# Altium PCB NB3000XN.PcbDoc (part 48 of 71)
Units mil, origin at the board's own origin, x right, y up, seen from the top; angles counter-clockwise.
Board outline 9527.56 x 6929.77 mil, 6 copper layers (Top Layer, GND+SHIELD, MidLayer1, MidLayer2, P2 - 3V3+5V0, Bottom Layer), stack 62.375 mil thick; 832 components, 1027 nets, 4655 pads, 4981 vias.
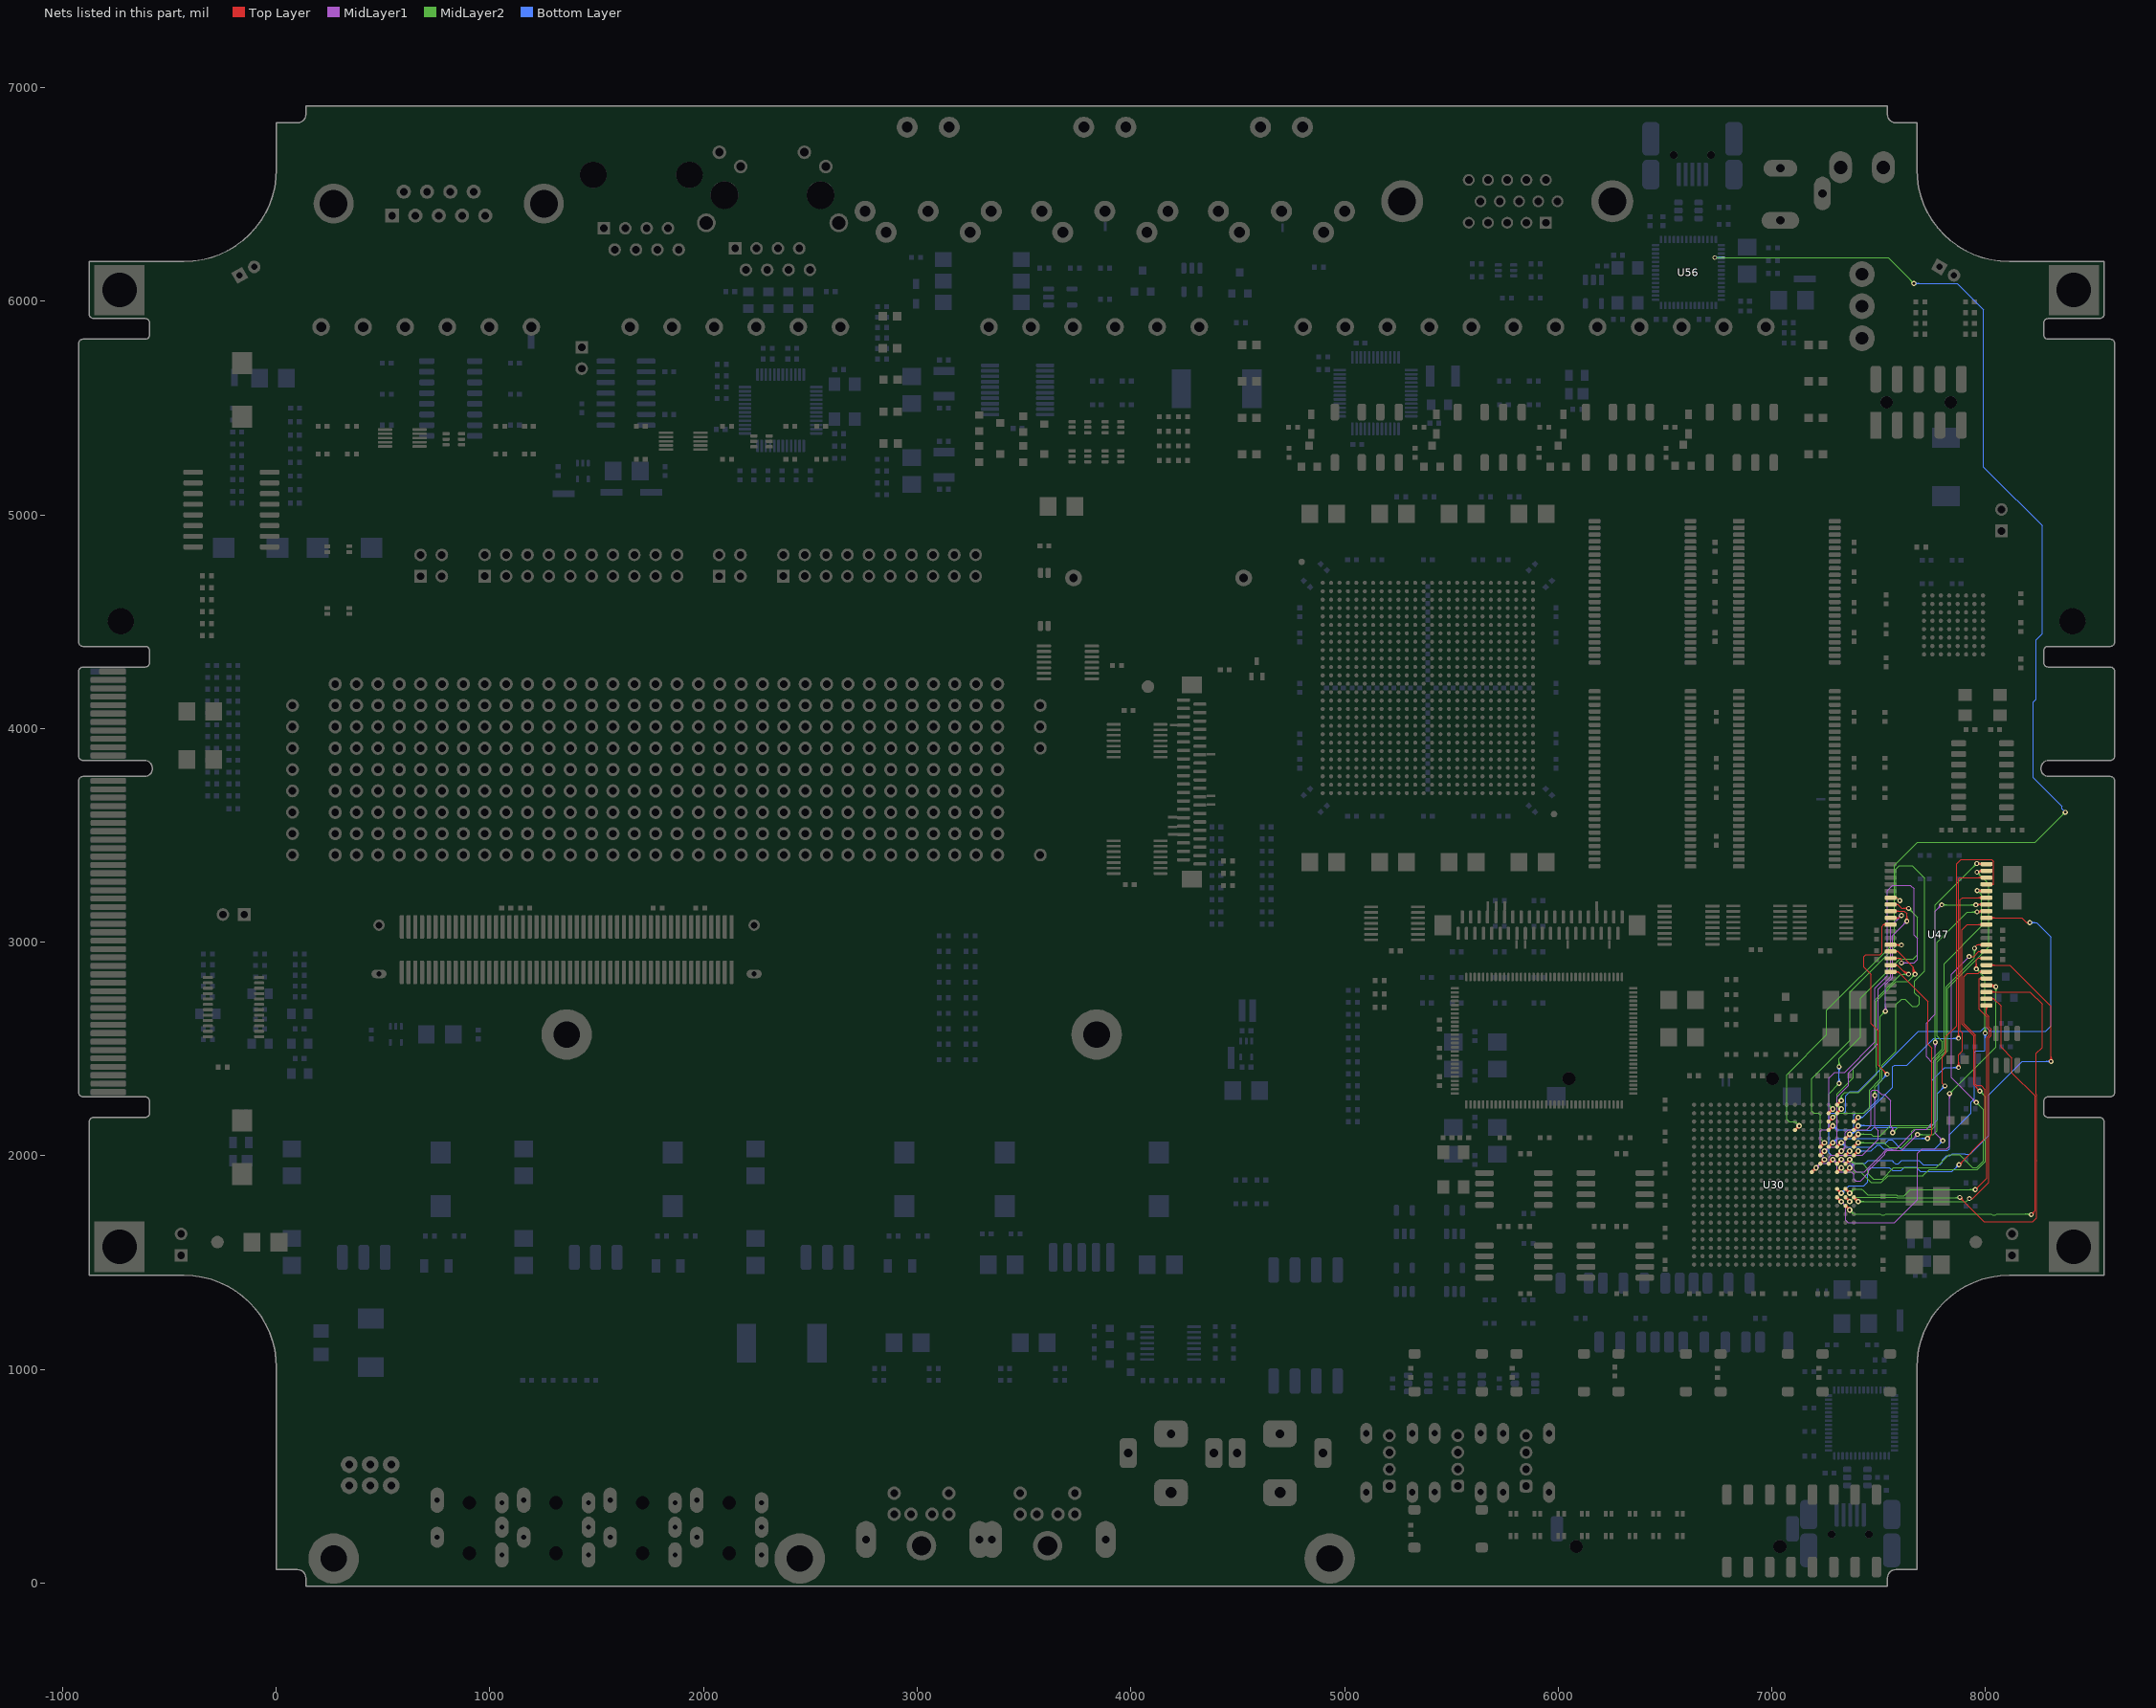
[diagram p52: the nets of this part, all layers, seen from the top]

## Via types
v1: diameter 23, hole 11.81, Top Layer to Bottom Layer, 3672 vias
v2: diameter 26, hole 11.81, Top Layer to Bottom Layer, 461 vias
v3: diameter 19, hole 11.81, Top Layer to Bottom Layer, tented both sides, 396 vias
v4: diameter 23.62, hole 11.81, Top Layer to Bottom Layer, 288 vias
v5: diameter 20, hole 11.81, Top Layer to Bottom Layer, 91 vias
v6: diameter 23, hole 11.81, Top Layer to Bottom Layer, tented both sides, 50 vias
v7: diameter 31, hole 11.81, Top Layer to Bottom Layer, 15 vias
v8: diameter 27.56, hole 11.81, Top Layer to Bottom Layer, tented both sides, 4 vias
v9: diameter 29, hole 11.81, Top Layer to Bottom Layer, 3 vias
v10: diameter 21, hole 11.81, Top Layer to Bottom Layer, 1 vias

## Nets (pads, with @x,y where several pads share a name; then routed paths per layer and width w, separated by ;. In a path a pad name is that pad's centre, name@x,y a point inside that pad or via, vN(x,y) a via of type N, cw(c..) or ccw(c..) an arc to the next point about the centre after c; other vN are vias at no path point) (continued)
HOST_SRAM.A10: U30.A12 U47.23 | length 1673.8
  Top Layer w4: v1(7924.52,1800.04) 7940.19,1800.04 8015.19,1875.04 8015.19,2551.39 8026.19,2562.39 8026.19,2593.36 8015.19,2604.36 8015.19,2652.98 8004.41,2663.76 U47.23@8004.41,2704.29 ; U47.23@7998.75,2698.64 cw(c7985.1,2684.98) 8004.41,2684.98 cw(c8023.72,2684.98) U47.23@8010.07,2698.64
  Top Layer w8: U30.A12@7384.02,1800.1 cw(c7384.02,1786) 7393.99,1795.97 cw(c7403.96,1805.94) U30.A12@7389.86,1805.94 ; U30.A12@7384.02,1805.94 v2(7403.7,1786.26) ; v2@7394.7,1786.26 ccw(c7372.97,1786.26) 7388.34,1801.62 ccw(c7403.7,1816.99) v2@7403.7,1795.26
  MidLayer2 w4: v2(7403.7,1786.26) 7910.74,1786.26 v1(7924.52,1800.04) ; v2@7408.65,1781.31 cw(c7420.6,1769.36) 7420.6,1786.26 cw(c7420.6,1803.16) v2@7408.65,1791.21 ; v2@7411.48,1778.48 cw(c7430.26,1759.7) 7430.26,1786.26 cw(c7430.26,1812.82) v2@7411.48,1794.04
HOST_SRAM.A11: U30.B13 U47.24 | length 2286.6
  Top Layer w4: U47.24@8004.41,2735.79 8038.52,2735.79 ; U47.24@8028.24,2730.82 cw(c8038.52,2722.66) 8038.52,2735.79 ; U47.24@8028.24,2740.76 ccw(c8038.52,2748.92) 8038.52,2735.79 ; v1(8213.86,1725.04) 8231.86,1743.04 8231.86,2280.52 8123.52,2388.85 8123.52,2458.37 8073.52,2508.37 8073.52,2700.79 8038.52,2735.79 ; v1@8213.86,1730.54 ccw(c8213.86,1743.82) 8223.25,1734.43 ccw(c8232.64,1725.04) v1@8219.36,1725.04 ; v1@8213.86,1734.54 ccw(c8213.86,1757.48) 8230.07,1741.26 ccw(c8246.29,1725.04) v1@8223.36,1725.04
  Top Layer w8: U30.B13@7344.65,1760.73 cw(c7344.65,1746.63) 7354.62,1756.6 cw(c7364.59,1766.57) U30.B13@7350.49,1766.57 ; U30.B13@7344.65,1766.57 v2(7364.33,1746.89) ; v2@7355.33,1746.89 ccw(c7333.6,1746.89) 7348.97,1762.25 ccw(c7364.33,1777.62) v2@7364.33,1755.89
  MidLayer2 w4: v2@7364.33,1735.89 cw(c7364.33,1709.33) 7383.11,1728.11 cw(c7401.89,1746.89) v2@7375.33,1746.89 ; v2@7364.33,1739.89 cw(c7364.33,1722.99) 7376.28,1734.94 cw(c7388.23,1746.89) v2@7371.33,1746.89 ; v2(7364.33,1746.89) 7383.51,1727.71 7507.1,1727.71 7512.62,1722.19 7527.38,1722.19 7532.9,1727.71 8027.1,1727.71 8032.62,1722.19 8047.38,1722.19 8052.9,1727.71 8211.19,1727.71 v1(8213.86,1725.04) ; 8184.48,1727.71 cw(c8184.48,1695.67) v1@8207.14,1718.32 ; 8194.14,1727.71 cw(c8194.14,1705.32) v1@8209.97,1721.15 ; 8197.36,1727.71 ccw(c8197.36,1741.54) v1@8207.14,1731.76
HOST_SRAM.A12: U30.B12 U47.25 | length 2457.9
  Top Layer w4: v1@7879.86,1795.87 cw(c7879.86,1772.94) 7896.07,1789.16 cw(c7912.29,1805.37) v1@7889.36,1805.37 ; v1@7879.86,1799.87 cw(c7879.86,1786.6) 7889.25,1795.99 cw(c7898.64,1805.37) v1@7885.36,1805.37 ; v1(7879.86,1805.37) 7993.52,1691.71 8221.86,1691.71 8240.19,1710.04 8240.19,1977.41 8240.03,1977.57 8240.03,1989.17 8240.19,1989.34 8240.19,2283.5 8237,2286.69 8237,2479.85 8265.19,2508.04 8265.19,2709.81 8207.72,2767.28 U47.25@8004.41,2767.28 ; U47.25@8027.63,2761.63 cw(c8041.28,2747.97) 8041.28,2767.28 cw(c8041.28,2786.6) U47.25@8027.63,2772.94
  Top Layer w8: U30.B12@7344.65,1800.1 cw(c7344.65,1786) 7354.62,1795.97 cw(c7364.59,1805.94) U30.B12@7350.49,1805.94 ; U30.B12@7344.65,1805.94 v2(7364.33,1786.26) ; v2@7355.33,1786.26 ccw(c7333.6,1786.26) 7348.97,1801.62 ccw(c7364.33,1816.99) v2@7364.33,1795.26
  MidLayer2 w4: v2(7364.33,1786.26) 7364.56,1786.26 7383.67,1805.37 7583.12,1805.37 7584.31,1804.19 7878.67,1804.19 v1(7879.86,1805.37) ; 7854.06,1804.19 ccw(c7854.06,1831.17) v1@7873.14,1812.09 ; 7859.78,1804.19 cw(c7859.78,1785.3) v1@7873.14,1798.66 ; 7863.72,1804.19 ccw(c7863.72,1821.52) v1@7875.97,1809.26
HOST_SRAM.A13: U30.C12 U47.26 | length 2133.8
  Top Layer w4: U47.26@8004.41,2798.78 v1@8041.12,2798.78 ; U47.26@8007.71,2798.78 cw(c8007.71,2750.56) v1@8041.81,2784.66 ; U47.26@8017.37,2798.78 cw(c8017.37,2760.22) v1@8044.64,2787.49 ; U47.26@8027.03,2798.78 cw(c8027.03,2769.88) v1@8047.46,2790.31 ; U47.26@8027.66,2793.16 cw(c8041.12,2779.86) v1@8041.12,2798.78 ; U47.26@8027.66,2804.4 ccw(c8041.12,2817.7) v1@8041.12,2798.78 ; 8036.68,2798.78 cw(c8036.68,2779.53) v1@8050.29,2793.14 ; v1(8048.52,2791.37) v1@8041.12,2798.78
  Top Layer w8: U30.C12@7305.28,1800.1 cw(c7305.28,1786) 7315.25,1795.97 cw(c7325.22,1805.94) U30.C12@7311.12,1805.94 ; U30.C12@7305.28,1805.94 v2(7324.96,1786.26) ; v2@7315.96,1786.26 ccw(c7294.23,1786.26) 7309.6,1801.62 ccw(c7324.96,1816.99) v2@7324.96,1795.26
  MidLayer1 w4: v2(7324.96,1786.26) 7344.51,1766.71 7345.33,1765.89 7345.33,1699.65 7356.46,1688.52 7574.67,1688.52 7681.86,1795.71 7681.86,2011.71 7703.52,2033.37 7819.19,2033.37 7831.86,2046.04 v1(7831.86,2291.71) ; v1@7825.14,2284.99 cw(c7808.92,2268.77) 7831.86,2268.77 cw(c7854.79,2268.77) v1@7838.57,2284.99 ; v1@7827.97,2287.82 cw(c7818.58,2278.43) 7831.86,2278.43 cw(c7845.14,2278.43) v1@7835.75,2287.82
  MidLayer2 w4: v1(7831.86,2291.71) 8048.52,2508.37 v1(8048.52,2791.37) ; v1@7831.86,2297.21 ccw(c7831.86,2310.49) 7841.25,2301.1 ccw(c7850.64,2291.71) v1@7837.36,2291.71 ; v1@7831.86,2301.21 ccw(c7831.86,2324.14) 7848.07,2307.93 ccw(c7864.29,2291.71) v1@7841.36,2291.71 ; v1@8041.81,2784.66 cw(c8025.59,2768.44) 8048.52,2768.44 cw(c8071.46,2768.44) v1@8055.24,2784.66 ; v1@8044.64,2787.49 cw(c8035.25,2778.1) 8048.52,2778.1 cw(c8061.8,2778.1) v1@8052.41,2787.49
HOST_SRAM.A14: U30.B11 U47.27 | length 1976.1
  Top Layer w4: v1(7951.86,1841.71) 8006.86,1896.71 8006.86,2554.37 8017.86,2565.37 8017.86,2590.37 8006.86,2601.37 8006.86,2650 7970.19,2686.67 7970.19,2828.61 7971.86,2830.28 ; v1@7951.86,1847.21 ccw(c7951.86,1860.49) 7961.25,1851.1 ccw(c7970.64,1841.71) v1@7957.36,1841.71 ; v1@7951.86,1851.21 ccw(c7951.86,1874.14) 7968.07,1857.93 ccw(c7984.29,1841.71) v1@7961.36,1841.71 ; U47.27@7980.2,2825.82 ccw(c7971.86,2820.23) 7971.86,2830.28 ; U47.27@7980.2,2834.73 cw(c7971.86,2840.32) 7971.86,2830.28 ; U47.27@8004.41,2830.28 7971.86,2830.28
  Top Layer w8: U30.B11@7344.65,1839.47 cw(c7344.65,1825.37) 7354.62,1835.34 cw(c7364.59,1845.31) U30.B11@7350.49,1845.31 ; U30.B11@7344.65,1845.31 v2(7364.33,1825.63) ; v2@7355.33,1825.63 ccw(c7333.6,1825.63) 7348.97,1840.99 ccw(c7364.33,1856.36) v2@7364.33,1834.63
  MidLayer2 w4: v2(7364.33,1825.63) 7383.7,1845 7420.23,1845 7428.18,1837.05 7448.52,1816.71 7583.1,1816.71 7587.62,1812.19 7619.01,1812.19 7648.52,1841.71 v1(7951.86,1841.71) ; v2@7364.33,1832.63 ccw(c7364.33,1849.53) 7376.28,1837.58 ccw(c7388.23,1825.63) v2@7371.33,1825.63 ; v2@7364.33,1836.63 ccw(c7364.33,1863.19) 7383.11,1844.41 ccw(c7401.89,1825.63) v2@7375.33,1825.63 ; v1@7945.14,1834.99 ccw(c7928.92,1818.77) 7928.92,1841.71 ccw(c7928.92,1864.64) v1@7945.14,1848.43 ; v1@7947.97,1837.82 ccw(c7938.58,1828.43) 7938.58,1841.71 ccw(c7938.58,1854.99) v1@7947.97,1845.6
HOST_SRAM.A15: U30.A3 U47.42 | length 1813.2
  Top Layer w4: v1@7866.81,2556.76 ccw(c7850.59,2572.98) 7873.52,2572.98 ccw(c7896.46,2572.98) v1@7880.24,2556.76 ; v1@7869.64,2553.93 ccw(c7860.25,2563.32) 7873.52,2563.32 ccw(c7886.8,2563.32) v1@7877.41,2553.93 ; v1(7873.52,2550.04) 7873.52,3215 7873.52,3298.52 7877.72,3302.72 U47.42@8004.41,3302.72 ; U47.42@7981.19,3297.06 ccw(c7967.54,3283.4) 7967.54,3302.72 ccw(c7967.54,3322.03) U47.42@7981.19,3308.37
  Top Layer w8: U30.A3@7384.02,2160.28 v2(7403.7,2179.96) ; U30.A3@7384.02,2166.12 ccw(c7384.02,2180.22) 7393.99,2170.25 ccw(c7403.96,2160.28) U30.A3@7389.86,2160.28 ; v2@7394.7,2179.96 cw(c7372.97,2179.96) 7388.34,2164.6 cw(c7403.7,2149.23) v2@7403.7,2170.96
  Bottom Layer w4: v2(7403.7,2179.96) 7423.52,2179.96 ; v2@7413.03,2174.14 cw(c7423.52,2167.6) 7423.52,2179.96 ; v2@7413.03,2185.78 ccw(c7423.52,2192.32) 7423.52,2179.96 ; v1@7866.81,2543.32 ccw(c7850.59,2527.11) 7850.59,2550.04 ccw(c7850.59,2572.98) v1@7866.81,2556.76 ; v1@7869.64,2546.15 ccw(c7860.25,2536.76) 7860.25,2550.04 ccw(c7860.25,2563.32) v1@7869.64,2553.93 ; v1(7873.52,2550.04) 7756.86,2550.04 7631.86,2425.04 7573.52,2425.04 7565.19,2416.71 7565.19,2321.63 7423.52,2179.96
HOST_SRAM.A16: U30.D8 U47.43 | length 2485.4
  Top Layer w4: v1(7959.86,3328.04) 7966.03,3334.21 U47.43@8004.41,3334.21 ; v1@7960.92,3326.98 cw(c7978.38,3309.52) U47.43@7978.38,3334.21 ; v1@7963.75,3324.15 cw(c7988.04,3299.86) U47.43@7988.04,3334.21 ; v1@7966.57,3321.32 cw(c7997.69,3290.21) U47.43@7997.69,3334.21 ; U47.43@7981.19,3328.56 ccw(c7967.54,3314.9) 7967.54,3334.21 ccw(c7967.54,3353.53) U47.43@7981.19,3339.87
  Top Layer w8: U30.D8@7265.91,1963.43 v2(7285.59,1983.11) ; U30.D8@7265.91,1969.27 ccw(c7265.91,1983.37) 7275.88,1973.4 ccw(c7285.85,1963.43) U30.D8@7271.75,1963.43 ; v2@7276.59,1983.11 cw(c7254.86,1983.11) 7270.23,1967.75 cw(c7285.59,1952.38) v2@7285.59,1974.11
  MidLayer1 w4: v2@7285.59,1972.11 cw(c7285.59,1945.55) 7304.37,1964.33 cw(c7323.15,1983.11) v2@7296.59,1983.11 ; v2@7285.59,1976.11 cw(c7285.59,1959.21) 7297.54,1971.16 cw(c7309.49,1983.11) v2@7292.59,1983.11 ; v2(7285.59,1983.11) 7305.86,1962.84 7305.86,1925.04 7306.19,1924.71 7373.52,1924.71 7383.52,1914.71 7383.52,1891.71 7391.86,1883.37 7415.19,1883.37 7453.52,1921.71 7453.52,1932.37 7529.88,2008.73 7529.88,2013.78 7541.15,2025.04 7606.86,2025.04 v1(7681.86,2100.04) ; v1@7672.36,2100.04 cw(c7649.42,2100.04) 7665.64,2083.82 cw(c7681.86,2067.61) v1@7681.86,2090.54 ; v1@7676.36,2100.04 cw(c7663.08,2100.04) 7672.47,2090.65 cw(c7681.86,2081.26) v1@7681.86,2094.54
  MidLayer2 w4: v1(7681.86,2100.04) 7755,2100.04 7773.19,2118.23 7773.19,2440.77 7823.52,2491.1 7823.52,2784.71 8015.19,2976.37 8015.19,3272.71 v1(7959.86,3328.04) ; v1@7685.75,2096.15 cw(c7695.14,2086.76) 7695.14,2100.04 cw(c7695.14,2113.32) v1@7685.75,2103.93 ; v1@7688.57,2093.32 cw(c7704.79,2077.11) 7704.79,2100.04 cw(c7704.79,2122.98) v1@7688.57,2106.76 ; v1@7959.86,3318.54 cw(c7959.86,3295.61) 7976.07,3311.82 cw(c7992.29,3328.04) v1@7969.36,3328.04 ; v1@7959.86,3322.54 cw(c7959.86,3309.26) 7969.25,3318.65 cw(c7978.64,3328.04) v1@7965.36,3328.04
HOST_SRAM.A17: U30.C6 U47.44 | length 2489.4
  Top Layer w4: v1(7959.52,3368.37) 7962.19,3365.71 U47.44@8004.41,3365.71 ; v1@7963.41,3372.26 ccw(c7979.24,3388.09) U47.44@7979.24,3365.71 ; v1@7966.24,3361.66 cw(c7976.02,3351.88) 7976.02,3365.71 ; v1@7966.24,3375.09 ccw(c7988.9,3397.75) U47.44@7988.9,3365.71 ; U47.44@7981.19,3360.05 ccw(c7967.54,3346.39) 7967.54,3365.71 ccw(c7967.54,3385.02) U47.44@7981.19,3371.37
  Top Layer w8: U30.C6@7305.28,2042.17 v2(7324.96,2061.85) ; U30.C6@7305.28,2048.01 ccw(c7305.28,2062.11) 7315.25,2052.14 ccw(c7325.22,2042.17) U30.C6@7311.12,2042.17 ; v2@7315.96,2061.85 cw(c7294.23,2061.85) 7309.6,2046.49 cw(c7324.96,2031.12) v2@7324.96,2052.85
  MidLayer1 w4: v1@7758.47,2524.99 cw(c7742.26,2508.77) 7765.19,2508.77 cw(c7788.13,2508.77) v1@7771.91,2524.99 ; v1@7761.3,2527.82 cw(c7751.91,2518.43) 7765.19,2518.43 cw(c7778.47,2518.43) v1@7769.08,2527.82 ; v1(7765.19,2531.71) 7765.19,2106.37 v1(7800.52,2071.04) ; v1@7791.02,2071.04 ccw(c7768.09,2071.04) 7784.31,2087.26 ccw(c7800.52,2103.48) v1@7800.52,2080.54 ; v1@7795.02,2071.04 ccw(c7781.75,2071.04) 7791.14,2080.43 ccw(c7800.52,2089.82) v1@7800.52,2076.54
  MidLayer2 w4: v1@7758.47,2538.43 ccw(c7742.26,2554.64) 7765.19,2554.64 ccw(c7788.13,2554.64) v1@7771.91,2538.43 ; v1@7761.3,2535.6 ccw(c7751.91,2544.99) 7765.19,2544.99 ccw(c7778.47,2544.99) v1@7769.08,2535.6 ; v1(7765.19,2531.71) 7765.19,3174.04 v1(7959.52,3368.37) ; v1@7950.02,3368.37 cw(c7927.09,3368.37) 7943.31,3352.16 cw(c7959.52,3335.94) v1@7959.52,3358.87 ; v1@7954.02,3368.37 cw(c7940.75,3368.37) 7950.14,3358.99 cw(c7959.52,3349.6) v1@7959.52,3362.87
  Bottom Layer w4: v2@7324.96,2050.85 cw(c7324.96,2024.29) 7343.74,2043.07 cw(c7362.52,2061.85) v2@7335.96,2061.85 ; v2@7324.96,2054.85 cw(c7324.96,2037.95) 7336.91,2049.9 cw(c7348.86,2061.85) v2@7331.96,2061.85 ; v2(7324.96,2061.85) 7345.1,2041.71 7465.19,2041.71 7481.86,2058.37 7532.11,2058.37 7548.28,2074.54 7562.77,2074.54 7603.94,2033.37 7762.86,2033.37 v1(7800.52,2071.04) ; v1@7791.02,2071.04 cw(c7768.09,2071.04) 7784.31,2054.82 cw(c7800.52,2038.61) v1@7800.52,2061.54 ; v1@7795.02,2071.04 cw(c7781.75,2071.04) 7791.13,2061.65 cw(c7800.52,2052.26) v1@7800.52,2065.54
HOST_SRAM.A18: U30.C11 U47.28 | length 2072.5
  Top Layer w4: v1(7876.19,1958.37) 7998.52,2080.71 7998.52,2310 7978.52,2330 7957.88,2330 7953,2334.88 7953,2540 ; v1@7876.19,1963.87 ccw(c7876.19,1977.15) 7885.58,1967.76 ccw(c7894.97,1958.37) v1@7881.69,1958.37 ; v1@7876.19,1967.87 ccw(c7876.19,1990.81) 7892.41,1974.59 ccw(c7908.63,1958.37) v1@7885.69,1958.37 ; 7953,2562 7953,2540 ; U47.28@7980.23,2857.29 ccw(c7971.77,2851.56) 7971.77,2861.77 ; U47.28@7980.23,2866.26 cw(c7971.77,2871.98) 7971.77,2861.77 ; U47.28@8004.41,2861.77 7971.77,2861.77 ; 7953,2540 7953,2565.21 7898.19,2620.02 7898.19,2838 7915.19,2855 7965,2855 7971.77,2861.77
  Top Layer w8: U30.C11@7305.28,1839.47 cw(c7305.28,1825.37) 7315.25,1835.34 cw(c7325.22,1845.31) U30.C11@7311.12,1845.31 ; U30.C11@7305.28,1845.31 v2(7324.96,1825.63) ; v2@7315.96,1825.63 ccw(c7294.23,1825.63) 7309.6,1840.99 ccw(c7324.96,1856.36) v2@7324.96,1834.63
  Bottom Layer w4: v2(7324.96,1825.63) 7360.33,1861 7430.96,1861 7448.02,1878.06 7448.02,1929.27 7463.13,1944.37 7550.62,1944.37 7564.5,1930.5 7605.5,1930.5 7621.21,1946.21 7674.45,1946.21 7694.66,1926 7843.82,1926 v1(7876.19,1958.37) ; v2@7324.96,1832.63 ccw(c7324.96,1849.53) 7336.91,1837.58 ccw(c7348.86,1825.63) v2@7331.96,1825.63 ; v2@7324.96,1836.63 ccw(c7324.96,1863.19) 7343.74,1844.41 ccw(c7362.52,1825.63) v2@7335.96,1825.63 ; v1@7866.69,1958.37 cw(c7843.76,1958.37) 7859.97,1942.16 cw(c7876.19,1925.94) v1@7876.19,1948.87 ; v1@7870.69,1958.37 cw(c7857.41,1958.37) 7866.8,1948.99 cw(c7876.19,1939.6) v1@7876.19,1952.87
HOST_SRAM.D0: U30.D2 U47.7 | length 1782
  Top Layer w4: U47.7@7555.59,3176.73 7589.52,3176.73 ; U47.7@7579.46,3171.82 cw(c7589.52,3163.97) 7589.52,3176.73 ; U47.7@7579.46,3181.65 ccw(c7589.52,3189.49) 7589.52,3176.73 ; v1@7633.47,3151.66 ccw(c7617.26,3135.44) 7617.26,3158.37 ccw(c7617.26,3181.31) v1@7633.47,3165.09 ; v1@7636.3,3154.49 ccw(c7626.91,3145.1) 7626.91,3158.37 ccw(c7626.91,3171.65) v1@7636.3,3162.26 ; v1(7640.19,3158.37) 7607.88,3158.37 7589.52,3176.73
  Top Layer w8: U30.D2@7265.91,2199.65 v2(7285.59,2219.33) ; U30.D2@7265.91,2205.49 ccw(c7265.91,2219.59) 7275.88,2209.62 ccw(c7285.85,2199.65) U30.D2@7271.75,2199.65 ; v2@7276.59,2219.33 cw(c7254.86,2219.33) 7270.23,2203.97 cw(c7285.59,2188.6) v2@7285.59,2210.33
  MidLayer2 w4: v2@7274.59,2219.33 ccw(c7248.03,2219.33) 7266.81,2238.11 ccw(c7285.59,2256.89) v2@7285.59,2230.33 ; v2@7278.59,2219.33 ccw(c7261.69,2219.33) 7273.64,2231.28 ccw(c7285.59,2243.23) v2@7285.59,2226.33 ; v2(7285.59,2219.33) 7266.52,2238.4 7266.52,2290.37 v1(7315.19,2339.04) ; v1@7305.69,2339.04 cw(c7282.76,2339.04) 7298.97,2322.82 cw(c7315.19,2306.61) v1@7315.19,2329.54 ; v1@7308.47,2423.43 ccw(c7292.26,2439.64) 7315.19,2439.64 ccw(c7338.13,2439.64) v1@7321.91,2423.43 ; v1@7309.69,2339.04 cw(c7296.41,2339.04) 7305.8,2329.65 cw(c7315.19,2320.26) v1@7315.19,2333.54 ; v1@7311.3,2420.6 ccw(c7301.91,2429.99) 7315.19,2429.99 ccw(c7328.47,2429.99) v1@7319.08,2420.6 ; v1(7315.19,2416.71) 7315.19,2456.06 7415.19,2556.06 7415.19,2737.71 7599.52,2922.04 7662.19,2922.04 7681.86,2941.71 7681.86,3116.71 v1(7640.19,3158.37) ; v1@7640.19,3148.87 cw(c7640.19,3125.94) 7656.41,3142.16 cw(c7672.63,3158.37) v1@7649.69,3158.37 ; v1@7640.19,3152.87 cw(c7640.19,3139.6) 7649.58,3148.99 cw(c7658.97,3158.37) v1@7645.69,3158.37
  Bottom Layer w4: v1@7308.47,2345.76 ccw(c7292.26,2361.98) 7315.19,2361.98 ccw(c7338.13,2361.98) v1@7321.91,2345.76 ; v1@7308.47,2409.99 cw(c7292.26,2393.77) 7315.19,2393.77 cw(c7338.13,2393.77) v1@7321.91,2409.99 ; v1@7311.3,2342.93 ccw(c7301.91,2352.32) 7315.19,2352.32 ccw(c7328.47,2352.32) v1@7319.08,2342.93 ; v1@7311.3,2412.82 cw(c7301.91,2403.43) 7315.19,2403.43 cw(c7328.47,2403.43) v1@7319.08,2412.82 ; v1(7315.19,2339.04) v1(7315.19,2416.71)
HOST_SRAM.D1: U30.D3 U47.8 | length 1662.2
  Top Layer w4: U47.8@7555.59,3145.24 7620,3145.24 7631.86,3133.37 v1(7631.86,3098.04) ; U47.8@7578.81,3139.58 cw(c7592.46,3125.92) 7592.46,3145.24 cw(c7592.46,3164.55) U47.8@7578.81,3150.89 ; v1@7625.14,3104.76 ccw(c7608.92,3120.98) 7631.86,3120.98 ccw(c7654.79,3120.98) v1@7638.57,3104.76 ; v1@7627.97,3101.93 ccw(c7618.58,3111.32) 7631.86,3111.32 ccw(c7645.14,3111.32) v1@7635.75,3101.93
  Top Layer w8: U30.D3@7265.91,2160.28 v2(7285.59,2179.96) ; U30.D3@7265.91,2166.12 ccw(c7265.91,2180.22) 7275.88,2170.25 ccw(c7285.85,2160.28) U30.D3@7271.75,2160.28 ; v2@7276.59,2179.96 cw(c7254.86,2179.96) 7270.23,2164.6 cw(c7285.59,2149.23) v2@7285.59,2170.96
  MidLayer1 w4: v1@7525.14,2683.43 ccw(c7508.92,2699.64) 7531.86,2699.64 ccw(c7554.79,2699.64) v1@7538.57,2683.43 ; v1@7527.97,2680.6 ccw(c7518.58,2689.99) 7531.86,2689.99 ccw(c7545.14,2689.99) v1@7535.75,2680.6 ; v1(7531.86,2676.71) 7531.86,2801.81 7564.86,2834.81 7564.86,3031.04 v1(7631.86,3098.04) ; v1@7622.36,3098.04 cw(c7599.42,3098.04) 7615.64,3081.82 cw(c7631.86,3065.61) v1@7631.86,3088.54 ; v1@7626.36,3098.04 cw(c7613.08,3098.04) 7622.47,3088.65 cw(c7631.86,3079.26) v1@7631.86,3092.54
  MidLayer2 w4: v2(7285.59,2179.96) 7305.67,2200.04 7431.86,2200.04 7456.86,2225.04 7456.86,2308.37 7506.86,2358.37 7506.86,2651.71 v1(7531.86,2676.71) ; v2@7285.59,2186.96 ccw(c7285.59,2203.86) 7297.54,2191.91 ccw(c7309.49,2179.96) v2@7292.59,2179.96 ; v2@7285.59,2190.96 ccw(c7285.59,2217.52) 7304.37,2198.74 ccw(c7323.15,2179.96) v2@7296.59,2179.96 ; v1@7522.36,2676.71 cw(c7499.42,2676.71) 7515.64,2660.49 cw(c7531.86,2644.27) v1@7531.86,2667.21 ; v1@7526.36,2676.71 cw(c7513.08,2676.71) 7522.47,2667.32 cw(c7531.86,2657.93) v1@7531.86,2671.21
HOST_SRAM.D2: U30.E7 U47.9 | length 1570.2
  Top Layer w4: U47.9@7555.59,3113.74 7595.56,3113.74 v1(7606.86,3125.04) ; U47.9@7578.81,3108.08 cw(c7592.46,3094.43) 7592.46,3113.74 cw(c7592.46,3133.05) U47.9@7578.81,3119.4
  Top Layer w8: U30.E7@7226.54,2002.8 v2(7246.22,2022.48) ; U30.E7@7226.54,2008.64 ccw(c7226.54,2022.74) 7236.51,2012.77 ccw(c7246.48,2002.8) U30.E7@7232.38,2002.8 ; v2@7237.22,2022.48 cw(c7215.49,2022.48) 7230.86,2007.12 cw(c7246.22,1991.75) v2@7246.22,2013.48
  MidLayer1 w4: v2(7246.22,2022.48) 7265.45,2041.71 7304.19,2041.71 7305.86,2043.37 7305.86,2276.37 7360.15,2330.67 7360.15,2388.84 7498.52,2527.21 7498.52,2779.79 7556.86,2838.12 7556.86,3075.04 v1(7606.86,3125.04) ; v2@7246.22,2029.48 ccw(c7246.22,2046.38) 7258.17,2034.43 ccw(c7270.12,2022.48) v2@7253.22,2022.48 ; v2@7246.22,2033.48 ccw(c7246.22,2060.04) 7265,2041.26 ; v2@7257.22,2022.48 cw(c7283.77,2022.48) 7265,2041.26 ; v1@7597.36,3125.04 cw(c7574.42,3125.04) 7590.64,3108.82 cw(c7606.86,3092.61) v1@7606.86,3115.54 ; v1@7601.36,3125.04 cw(c7588.08,3125.04) 7597.47,3115.65 cw(c7606.86,3106.26) v1@7606.86,3119.54
HOST_SRAM.D3: U30.D4 U47.10 | length 1589.1
  Top Layer w4: v1@7530.69,2382.04 ccw(c7507.76,2382.04) 7523.97,2398.26 ccw(c7540.19,2414.48) v1@7540.19,2391.54 ; U47.10@7531.35,3077.85 ccw(c7523.19,3072.48) 7523.19,3082.24 ; U47.10@7531.35,3086.64 cw(c7523.19,3092.01) 7523.19,3082.24 ; v1@7534.69,2382.04 ccw(c7521.41,2382.04) 7530.8,2391.43 ccw(c7540.19,2400.82) v1@7540.19,2387.54 ; v1(7540.19,2382.04) 7498.52,2423.71 7498.52,2586.04 7465.19,2619.37 7465.19,2850.04 7431.86,2883.37 7431.86,2933.37 7440.19,2941.71 7506.86,2941.71 7515.19,2950.04 7515.19,3074.24 7523.19,3082.24 ; U47.10@7555.59,3082.24 7523.19,3082.24
  Top Layer w8: U30.D4@7265.91,2120.91 v2(7285.59,2140.59) ; U30.D4@7265.91,2126.75 ccw(c7265.91,2140.85) 7275.88,2130.88 ccw(c7285.85,2120.91) U30.D4@7271.75,2120.91 ; v2@7276.59,2140.59 cw(c7254.86,2140.59) 7270.23,2125.23 cw(c7285.59,2109.86) v2@7285.59,2131.59
  Bottom Layer w4: v2@7285.59,2129.59 cw(c7285.59,2103.03) 7304.37,2121.81 cw(c7323.14,2140.59) v2@7296.59,2140.59 ; v2@7285.59,2133.59 cw(c7285.59,2116.69) 7297.54,2128.64 cw(c7309.49,2140.59) v2@7292.59,2140.59 ; v2(7285.59,2140.59) 7305.14,2121.04 7373.52,2121.04 7383.86,2131.37 7383.86,2191.71 7392.19,2200.04 7431.86,2200.04 7499.86,2268.04 7499.86,2341.71 v1(7540.19,2382.04) ; v1@7530.69,2382.04 cw(c7507.76,2382.04) 7523.97,2365.82 cw(c7540.19,2349.61) v1@7540.19,2372.54 ; v1@7534.69,2382.04 cw(c7521.41,2382.04) 7530.8,2372.65 cw(c7540.19,2363.26) v1@7540.19,2376.54
HOST_SRAM.D4: U30.E6 U47.13 | length 1379.6
  Top Layer w4: U47.13@7555.59,2987.76 7589.52,2987.76 ; U47.13@7579.46,2982.84 cw(c7589.52,2975) 7589.52,2987.76 ; U47.13@7579.46,2992.67 ccw(c7589.52,3000.51) 7589.52,2987.76 ; v1@7598.59,2982.03 ccw(c7590.57,2977.5) 7590.57,2986.71 ; v1@7598.59,2991.38 cw(c7590.57,2995.92) 7590.57,2986.71 ; v1(7606.86,2986.71) 7590.57,2986.71 ; 7589.52,2987.76 7590.57,2986.71
  Top Layer w8: U30.E6@7226.54,2042.17 v2(7246.22,2061.85) ; U30.E6@7226.54,2048.01 ccw(c7226.54,2062.11) 7236.51,2052.14 ccw(c7246.48,2042.17) U30.E6@7232.38,2042.17 ; v2@7237.22,2061.85 cw(c7215.49,2061.85) 7230.86,2046.49 cw(c7246.22,2031.12) v2@7246.22,2052.85
  MidLayer2 w4: v2(7246.22,2061.85) 7227.19,2080.88 7227.19,2191.71 7218.86,2200.04 7195.86,2200.04 7187.52,2208.37 7187.52,2362.33 7366.19,2541 7366.19,2767.71 7585.19,2986.71 ; v1@7599.87,2980.27 ccw(c7585.19,2966.75) 7585.19,2986.71 ; v1@7599.87,2993.14 cw(c7585.19,3006.66) 7585.19,2986.71 ; v1@7602.81,2982.98 ccw(c7594.31,2975.15) 7594.31,2986.71 ccw(c7594.31,2998.26) v1@7602.81,2990.43 ; v1(7606.86,2986.71) 7585.19,2986.71
HOST_SRAM.D5: U30.C1 U47.14 | length 1277.1
  Top Layer w4: U47.14@7555.59,2956.26 7588.82,2956.26 ; U47.14@7579.63,2951.57 cw(c7588.82,2944.92) 7588.82,2956.26 ; U47.14@7579.63,2960.95 ccw(c7588.82,2967.6) 7588.82,2956.26 ; 7661.86,2860.89 ccw(c7677.37,2860.89) v1@7668.81,2847.96 ; 7661.86,2868.33 ccw(c7682.29,2868.33) v1@7671.02,2851.29 ; 7661.86,2875.78 ccw(c7687.21,2875.78) v1@7673.22,2854.63 ; v1(7670.19,2850.04) 7661.86,2858.37 7661.86,2883.22 ; v1@7675.43,2857.96 cw(c7692.13,2883.22) 7661.86,2883.22 ; 7588.82,2956.26 7661.86,2883.22
  Top Layer w8: U30.C1@7305.28,2239.02 v2(7324.96,2258.7) ; U30.C1@7305.28,2244.86 ccw(c7305.28,2258.96) 7315.25,2248.99 ccw(c7325.22,2239.02) U30.C1@7311.12,2239.02 ; v2@7315.96,2258.7 cw(c7294.23,2258.7) 7309.6,2243.34 cw(c7324.96,2227.97) v2@7324.96,2249.7
  MidLayer2 w4: v2@7318.61,2267.68 ccw(c7309.92,2279.96) 7324.96,2279.96 ; v2@7320.92,2264.42 ccw(c7315.39,2272.23) 7324.96,2272.23 ccw(c7334.53,2272.23) v2@7329,2264.42 ; v2(7324.96,2258.7) 7324.96,2279.96 ; v2@7331.31,2267.68 cw(c7340,2279.96) 7324.96,2279.96 ; v1@7660.69,2850.04 cw(c7637.76,2850.04) 7653.97,2833.82 cw(c7670.19,2817.61) v1@7670.19,2840.54 ; v1@7664.69,2850.04 cw(c7651.41,2850.04) 7660.8,2840.65 cw(c7670.19,2831.26) v1@7670.19,2844.54 ; v1(7670.19,2850.04) 7636.86,2816.71 7581.86,2816.71 7490.19,2725.04 7490.19,2415 7490.52,2414.67 7490.52,2381.69 7405.21,2296.37 7380,2296.37 7341.37,2296.37 7324.96,2279.96
HOST_SRAM.D6: U30.E8 U47.15 | length 2250.2
  Top Layer w4: U47.15@7555.59,2924.76 7600.24,2924.76 7606.86,2918.14 v1(7606.86,2902.71) ; U47.15@7578.81,2919.11 cw(c7592.46,2905.45) 7592.46,2924.76 cw(c7592.46,2944.08) U47.15@7578.81,2930.42
  Top Layer w8: U30.E8@7226.54,1963.43 v2(7246.22,1983.11) ; U30.E8@7226.54,1969.27 ccw(c7226.54,1983.37) 7236.51,1973.4 ccw(c7246.48,1963.43) U30.E8@7232.38,1963.43 ; v2@7237.22,1983.11 cw(c7215.49,1983.11) 7230.86,1967.75 cw(c7246.22,1952.38) v2@7246.22,1974.11
  MidLayer1 w4: v2@7238.44,1990.89 ccw(c7234.22,1995.11) 7240.19,1995.11 ; v2(7246.22,1983.11) 7240.19,1983.11 7240.19,2000.04 7226.19,2014.04 7226.19,2116.71 7230.52,2121.04 7256.86,2121.04 7266.52,2130.71 7266.52,2364.04 7294.19,2391.71 7340.39,2391.71 7481.86,2533.17 7481.86,2560 7481.86,2785.75 7540.19,2844.08 7540.19,3241.71 7565.19,3266.71 7648.52,3266.71 7665.19,3250.04 7665.19,3033.37 7681.86,3016.71 7681.86,2919.37 7665.19,2902.71 v1(7606.86,2902.71) ; v1@7610.75,2898.82 cw(c7620.14,2889.43) 7620.14,2902.71 cw(c7620.14,2915.99) v1@7610.75,2906.6 ; v1@7613.57,2895.99 cw(c7629.79,2879.77) 7629.79,2902.71 cw(c7629.79,2925.64) v1@7613.57,2909.43
HOST_SRAM.D7: U30.C2 U47.16 | length 1229.1
  Top Layer w4: U47.16@7555.59,2893.27 7587.15,2893.27 ; U47.16@7580.04,2889.21 cw(c7587.15,2885.02) 7587.15,2893.27 ; U47.16@7580.04,2897.33 ccw(c7587.15,2901.52) 7587.15,2893.27 ; 7607.22,2873.2 ccw(c7640.19,2906.17) v1@7640.19,2859.54 ; 7614.05,2866.37 ccw(c7640.19,2892.51) v1@7640.19,2855.54 ; 7620.88,2859.54 ccw(c7640.19,2878.86) v1@7640.19,2851.54 ; 7627.7,2852.71 ccw(c7640.19,2865.2) v1@7640.19,2847.54 ; v1(7640.19,2850.04) 7630.38,2850.04 7587.15,2893.27
  Top Layer w8: U30.C2@7305.28,2199.65 v2(7324.96,2219.33) ; U30.C2@7305.28,2205.49 ccw(c7305.28,2219.59) 7315.25,2209.62 ccw(c7325.22,2199.65) U30.C2@7311.12,2199.65 ; v2@7315.96,2219.33 cw(c7294.23,2219.33) 7309.6,2203.97 cw(c7324.96,2188.6) v2@7324.96,2210.33
  MidLayer2 w4: v2@7313.96,2219.33 ccw(c7287.4,2219.33) 7306.18,2238.11 ccw(c7324.96,2256.89) v2@7324.96,2230.33 ; v2@7317.96,2219.33 ccw(c7301.06,2219.33) 7313.01,2231.28 ccw(c7324.96,2243.23) v2@7324.96,2226.33 ; v2(7324.96,2219.33) 7305.86,2238.43 7305.86,2290.71 7381.86,2366.71 7381.86,2408.37 7481.86,2508.37 7481.86,2729.37 7602.52,2850.04 v1(7640.19,2850.04) ; v1@7633.47,2843.32 ccw(c7617.26,2827.11) 7617.26,2850.04 ccw(c7617.26,2872.98) v1@7633.47,2856.76 ; v1@7636.3,2846.15 ccw(c7626.91,2836.76) 7626.91,2850.04 ccw(c7626.91,2863.32) v1@7636.3,2853.93
HOST_SRAM.D8: U30.B9 U47.29 | length 2236.8
  Top Layer w4: U47.29@8004.41,2893.27 8113.63,2893.27 8306.86,2700.04 v1(8306.86,2441.71) ; U47.29@8027.63,2887.61 cw(c8041.28,2873.95) 8041.28,2893.27 cw(c8041.28,2912.58) U47.29@8027.63,2898.92 ; v1@8300.14,2448.43 ccw(c8283.92,2464.64) 8306.86,2464.64 ccw(c8329.79,2464.64) v1@8313.57,2448.43 ; v1@8302.97,2445.6 ccw(c8293.58,2454.99) 8306.86,2454.99 ccw(c8320.14,2454.99) v1@8310.75,2445.6
  Top Layer w8: U30.B9@7344.65,1924.06 v2(7364.33,1943.74) ; U30.B9@7344.65,1929.9 ccw(c7344.65,1944) 7354.62,1934.03 ccw(c7364.59,1924.06) U30.B9@7350.49,1924.06 ; v2@7355.33,1943.74 cw(c7333.6,1943.74) 7348.97,1928.38 cw(c7364.33,1913.01) v2@7364.33,1934.74
  Bottom Layer w4: v2(7364.33,1943.74) 7384.63,1964.04 7437.54,1964.04 7451.87,1978.37 7562.11,1978.37 7567.5,1972.98 7567.5,1972.75 7577.75,1962.5 7592.25,1962.5 7607.96,1978.21 7687.71,1978.21 7707.92,1958 7787.09,1958 7798.36,1969.27 7798.36,1980.58 7817.98,2000.21 7833.89,2000.21 7844.5,2010.81 7902.67,2010.81 7905.98,2007.5 7924.4,2007.5 7927.46,2010.56 7930.71,2010.56 8015.19,2095.04 8015.19,2285.04 8171.86,2441.71 v1(8306.86,2441.71) ; v2@7364.33,1950.74 ccw(c7364.33,1967.64) 7376.28,1955.69 ccw(c7388.23,1943.74) v2@7371.33,1943.74 ; v2@7364.33,1954.74 ccw(c7364.33,1981.3) 7383.11,1962.52 ccw(c7401.88,1943.74) v2@7375.33,1943.74 ; v1@8300.14,2434.99 ccw(c8283.92,2418.77) 8283.92,2441.71 ccw(c8283.92,2464.64) v1@8300.14,2448.43 ; v1@8302.97,2437.82 ccw(c8293.58,2428.43) 8293.58,2441.71 ccw(c8293.58,2454.99) v1@8302.97,2445.6
HOST_SRAM.D9: U30.A7 U47.30 | length 1908.4
  Top Layer w4: v1@7950.14,2881.76 ccw(c7933.92,2897.98) 7956.86,2897.98 ccw(c7979.79,2897.98) v1@7963.57,2881.76 ; v1@7952.97,2878.93 ccw(c7943.58,2888.32) 7956.86,2888.32 ccw(c7970.14,2888.32) v1@7960.75,2878.93 ; v1(7956.86,2875.04) 7956.86,2916.43 7965.19,2924.76 U47.30@8004.41,2924.76 ; U47.30@7981.19,2919.11 ccw(c7967.54,2905.45) 7967.54,2924.76 ccw(c7967.54,2944.08) U47.30@7981.19,2930.42
  Top Layer w8: U30.A7@7384.02,2002.8 v2(7403.7,2022.48) ; U30.A7@7384.02,2008.64 ccw(c7384.02,2022.74) 7393.99,2012.77 ccw(c7403.96,2002.8) U30.A7@7389.86,2002.8 ; v2@7394.7,2022.48 cw(c7372.97,2022.48) 7388.34,2007.12 cw(c7403.7,1991.75) v2@7403.7,2013.48
  MidLayer2 w4: v1@7956.86,2865.54 cw(c7956.86,2842.61) 7973.07,2858.82 cw(c7989.29,2875.04) v1@7966.36,2875.04 ; v1@7956.86,2869.54 cw(c7956.86,2856.26) 7966.25,2865.65 cw(c7975.64,2875.04) v1@7962.36,2875.04 ; v1(7956.86,2875.04) 7998.52,2833.37 v1(7998.52,2575.04) ; v1@7991.81,2581.76 ccw(c7975.59,2597.98) 7998.52,2597.98 ccw(c8021.46,2597.98) v1@8005.24,2581.76 ; v1@7994.64,2578.93 ccw(c7985.25,2588.32) 7998.52,2588.32 ccw(c8011.8,2588.32) v1@8002.41,2578.93
  Bottom Layer w4: v2(7403.7,2022.48) 7465.3,2022.48 7492.86,2050.04 7505.52,2050.04 7523.35,2032.21 7559.29,2032.21 7566.46,2025.04 7823.86,2025.04 7831.86,2033.04 7831.86,2100.04 7931.86,2200.04 7931.86,2251.37 7948.52,2268.04 7948.52,2485.71 7954.52,2491.71 7995.86,2491.71 7998.52,2494.37 v1(7998.52,2575.04) ; v2@7408.65,2017.53 cw(c7420.6,2005.58) 7420.6,2022.48 cw(c7420.6,2039.38) v2@7408.65,2027.43 ; v2@7411.48,2014.7 cw(c7430.26,1995.93) 7430.26,2022.48 cw(c7430.26,2049.04) v2@7411.48,2030.26 ; v1@7991.81,2568.32 cw(c7975.59,2552.11) 7998.52,2552.11 cw(c8021.46,2552.11) v1@8005.24,2568.32 ; v1@7994.64,2571.15 cw(c7985.25,2561.76) 7998.52,2561.76 cw(c8011.8,2561.76) v1@8002.41,2571.15
HOST_SRAM.D10: U30.B8 U47.31 | length 2200.1
  Top Layer w4: v1(7923.52,2933.37) 7945.97,2933.37 7968.85,2956.26 ; U47.31@7980.91,2950.9 ccw(c7968.85,2940.01) 7968.85,2956.26 ; U47.31@7980.91,2961.62 cw(c7968.85,2972.51) 7968.85,2956.26 ; U47.31@8004.41,2956.26 7968.85,2956.26
  Top Layer w8: U30.B8@7344.65,1963.43 v2(7364.33,1983.11) ; U30.B8@7344.65,1969.27 ccw(c7344.65,1983.37) 7354.62,1973.4 ccw(c7364.59,1963.43) U30.B8@7350.49,1963.43 ; v2@7355.33,1983.11 cw(c7333.6,1983.11) 7348.97,1967.75 cw(c7364.33,1952.38) v2@7364.33,1974.11
  MidLayer1 w4: v1(7923.52,2933.37) 7923.37,2933.37 7840.19,2850.19 7840.19,2366.71 v1(7956.86,2250.04) ; v1@7947.36,2250.04 ccw(c7924.42,2250.04) 7940.64,2266.26 ccw(c7956.86,2282.48) v1@7956.86,2259.54 ; v1@7951.36,2250.04 ccw(c7938.08,2250.04) 7947.47,2259.43 ccw(c7956.86,2268.82) v1@7956.86,2255.54
  MidLayer2 w4: v2@7364.33,1972.11 cw(c7364.33,1945.55) 7383.11,1964.33 cw(c7401.89,1983.11) v2@7375.33,1983.11 ; v2@7364.33,1976.11 cw(c7364.33,1959.21) 7376.28,1971.16 cw(c7388.23,1983.11) v2@7371.33,1983.11 ; v2(7364.33,1983.11) 7383.4,1964.04 7423.52,1964.04 7448.52,1939.04 7448.52,1918.37 7475.19,1891.71 7517.56,1891.71 7569.85,1944 7769,1944 7830,2005 7878,2005 7939,1944 7958.54,1944 7991.19,1976.65 7991.19,2215.71 v1(7956.86,2250.04) ; v1@7956.86,2240.54 cw(c7956.86,2217.61) 7973.07,2233.82 cw(c7989.29,2250.04) v1@7966.36,2250.04 ; v1@7956.86,2244.54 cw(c7956.86,2231.26) 7966.25,2240.65 cw(c7975.64,2250.04) v1@7962.36,2250.04
HOST_SRAM.D11: U30.A6 U47.32 | length 1642
  Top Layer w4: v1(7948.52,2972.04) 7948.52,2974.37 7961.91,2987.76 U47.32@8004.41,2987.76 ; U47.32@7981.19,2982.1 ccw(c7967.54,2968.44) 7967.54,2987.76 ccw(c7967.54,3007.07) U47.32@7981.19,2993.41
  Top Layer w8: U30.A6@7384.02,2042.17 v2(7403.7,2061.85) ; U30.A6@7384.02,2048.01 ccw(c7384.02,2062.11) 7393.99,2052.14 ccw(c7403.96,2042.17) U30.A6@7389.86,2042.17 ; v2@7394.7,2061.85 cw(c7372.97,2061.85) 7388.34,2046.49 cw(c7403.7,2031.12) v2@7403.7,2052.85
  MidLayer2 w4: v2(7403.7,2061.85) 7525.72,2061.85 7549.18,2038.39 7608.39,2038.39 7655,2085 7655,2115.04 7665,2125.04 7750,2125.04 7750,2125.37 7765,2140.37 7765,2150 ; v2@7408.65,2056.9 cw(c7420.6,2044.95) 7420.6,2061.85 cw(c7420.6,2078.75) v2@7408.65,2066.8 ; v2@7411.48,2054.07 cw(c7430.26,2035.3) 7430.26,2061.85 cw(c7430.26,2088.41) v2@7411.48,2069.63 ; 7765.19,2150 7765.19,2444.08 7815.19,2494.08 7815.19,2791.71 7948.52,2925.04 v1(7948.52,2972.04) ; v1@7941.81,2965.32 cw(c7925.59,2949.11) 7948.52,2949.11 cw(c7971.46,2949.11) v1@7955.24,2965.32 ; v1@7944.64,2968.15 cw(c7935.25,2958.76) 7948.52,2958.76 cw(c7961.8,2958.76) v1@7952.41,2968.15
HOST_SRAM.D12: U30.C9 U47.35 | length 2294.2
  Top Layer w4: v1@7964.02,2303.04 ccw(c7941.09,2303.04) 7957.31,2319.26 ccw(c7973.52,2335.48) v1@7973.52,2312.54 ; v1@7968.02,2303.04 ccw(c7954.75,2303.04) 7964.14,2312.43 ccw(c7973.52,2321.82) v1@7973.52,2308.54 ; v1(7973.52,2303.04) 7945,2331.56 7945,2561.9 7890.19,2616.71 7890.19,3058.37 7914.06,3082.24 U47.35@8004.41,3082.24 ; U47.35@7981.19,3076.59 ccw(c7967.54,3062.93) 7967.54,3082.24 ccw(c7967.54,3101.56) U47.35@7981.19,3087.9
  Top Layer w8: U30.C9@7305.28,1924.06 v2(7324.96,1943.74) ; U30.C9@7305.28,1929.9 ccw(c7305.28,1944) 7315.25,1934.03 ccw(c7325.22,1924.06) U30.C9@7311.12,1924.06 ; v2@7315.96,1943.74 cw(c7294.23,1943.74) 7309.6,1928.38 cw(c7324.96,1913.01) v2@7324.96,1934.74
  MidLayer2 w4: v2@7324.96,1932.74 cw(c7324.96,1906.18) 7343.74,1924.96 cw(c7362.52,1943.74) v2@7335.96,1943.74 ; v2@7324.96,1936.74 cw(c7324.96,1919.84) 7336.91,1931.79 cw(c7348.86,1943.74) v2@7331.96,1943.74 ; v2(7324.96,1943.74) 7343.99,1924.71 7415.52,1924.71 7465.19,1875.04 7512.21,1875.04 7544.67,1907.5 7708.32,1907.5 7709.19,1908.37 7736.82,1936 7961.86,1936 7999.19,1973.33 7999.19,2277.37 v1(7973.52,2303.04) ; v1@7973.52,2293.54 cw(c7973.52,2270.61) 7989.74,2286.82 cw(c8005.96,2303.04) v1@7983.02,2303.04 ; v1@7973.52,2297.54 cw(c7973.52,2284.26) 7982.91,2293.65 cw(c7992.3,2303.04) v1@7979.02,2303.04
HOST_SRAM.D13: U30.B7 U47.36 | length 2551.8
  Top Layer w4: U47.36@8004.41,3113.74 8169.49,3113.74 8191.52,3091.71 v1(8207.19,3091.71) ; U47.36@8027.63,3108.08 cw(c8041.28,3094.43) 8041.28,3113.74 cw(c8041.28,3133.05) U47.36@8027.63,3119.4
  Top Layer w8: U30.B7@7344.65,2002.8 v2(7364.33,2022.48) ; U30.B7@7344.65,2008.64 ccw(c7344.65,2022.74) 7354.62,2012.77 ccw(c7364.59,2002.8) U30.B7@7350.49,2002.8 ; v2@7355.33,2022.48 cw(c7333.6,2022.48) 7348.97,2007.12 cw(c7364.33,1991.75) v2@7364.33,2013.48
  Bottom Layer w4: v2@7353.33,2022.48 cw(c7326.77,2022.48) 7345.55,2003.7 cw(c7364.33,1984.93) v2@7364.33,2011.48 ; v2@7357.33,2022.48 cw(c7340.43,2022.48) 7352.38,2010.53 cw(c7364.33,1998.58) v2@7364.33,2015.48 ; v2(7364.33,2022.48) 7345.23,2003.37 7277.52,2003.37 7266.52,2014.37 7266.52,2191.71 7274.86,2200.04 7336.86,2200.04 7345.19,2208.37 7345.19,2280.04 7365.19,2300.04 7403.19,2300.04 7686.52,2583.37 7977.52,2583.37 7994.19,2600.04 8004.86,2600.04 8021.52,2583.37 8281.86,2583.37 8306.86,2608.37 8306.86,3025.04 8240.19,3091.71 v1(8207.19,3091.71) ; v1@8211.08,3087.82 cw(c8220.47,3078.43) 8220.47,3091.71 cw(c8220.47,3104.99) v1@8211.08,3095.6 ; v1@8213.91,3084.99 cw(c8230.13,3068.77) 8230.13,3091.71 cw(c8230.13,3114.64) v1@8213.91,3098.43
HOST_SRAM.D14: U30.A5 U47.37 | length 1851.7
  Top Layer w4: v1(7960.52,3141.71) 7964.05,3145.24 U47.37@8004.41,3145.24 ; v1@7961.58,3140.65 cw(c7972.66,3129.57) 7972.66,3145.24 ; v1@7964.41,3137.82 cw(c7982.32,3119.91) U47.37@7982.32,3145.24 ; v1@7967.24,3134.99 cw(c7991.98,3110.26) U47.37@7991.98,3145.24 ; v1@7967.24,3148.43 ccw(c7974.94,3156.13) 7974.94,3145.24 ; U47.37@7981.19,3139.58 ccw(c7967.54,3125.92) 7967.54,3145.24 ccw(c7967.54,3164.55) U47.37@7981.19,3150.89
  Top Layer w8: U30.A5@7384.02,2081.54 v2(7403.7,2101.22) ; U30.A5@7384.02,2087.38 ccw(c7384.02,2101.48) 7393.99,2091.51 ccw(c7403.96,2081.54) U30.A5@7389.86,2081.54 ; v2@7394.7,2101.22 cw(c7372.97,2101.22) 7388.34,2085.86 cw(c7403.7,2070.49) v2@7403.7,2092.22
  MidLayer2 w4: v2(7403.7,2101.22) 7463.59,2101.22 7472.62,2092.19 7507.34,2092.19 7556.86,2141.71 7738.52,2141.71 7748.52,2151.71 7748.52,2450.04 7798.52,2500.04 7798.52,2535 7773.19,2560.33 7773.19,2999.71 7798.52,3025.04 7915.19,3141.71 v1(7960.52,3141.71) ; v2@7408.65,2096.27 cw(c7420.6,2084.32) 7420.6,2101.22 cw(c7420.6,2118.12) v2@7408.65,2106.17 ; v2@7411.48,2093.44 cw(c7430.26,2074.67) 7430.26,2101.22 cw(c7430.26,2127.78) v2@7411.48,2109 ; v1@7953.81,3134.99 ccw(c7937.59,3118.77) 7937.59,3141.71 ccw(c7937.59,3164.64) v1@7953.81,3148.43 ; v1@7956.64,3137.82 ccw(c7947.25,3128.43) 7947.25,3141.71 ccw(c7947.25,3154.99) v1@7956.64,3145.6
HOST_SRAM.D15: U30.C8 U47.38 | length 2233.8
  Top Layer w4: v1(7954.86,3175.04) 7956.55,3176.73 U47.38@8004.41,3176.73 ; v1@7958.75,3171.15 cw(c7972.22,3157.68) 7972.22,3176.73 ; v1@7961.57,3168.32 cw(c7981.87,3148.02) U47.38@7981.87,3176.73 ; v1@7961.57,3181.76 ccw(c7973.71,3193.89) 7973.71,3176.73 ; U47.38@7981.19,3171.08 ccw(c7967.54,3157.42) 7967.54,3176.73 ccw(c7967.54,3196.05) U47.38@7981.19,3182.39
  Top Layer w8: U30.C8@7305.28,1963.43 v2(7324.96,1983.11) ; U30.C8@7305.28,1969.27 ccw(c7305.28,1983.37) 7315.25,1973.4 ccw(c7325.22,1963.43) U30.C8@7311.12,1963.43 ; v2@7315.96,1983.11 cw(c7294.23,1983.11) 7309.6,1967.75 cw(c7324.96,1952.38) v2@7324.96,1974.11
  MidLayer1 w4: v2@7324.96,1972.11 cw(c7324.96,1945.55) 7343.74,1964.33 cw(c7362.52,1983.11) v2@7335.96,1983.11 ; v2@7324.96,1976.11 cw(c7324.96,1959.21) 7336.91,1971.16 cw(c7348.86,1983.11) v2@7331.96,1983.11 ; v2(7324.96,1983.11) 7344.03,1964.04 7373.52,1964.04 7384.52,1953.04 7384.52,1935.71 7395.52,1924.71 7433.19,1924.71 7521.88,2013.4 7521.88,2017.09 7538.17,2033.37 7582.86,2033.37 7668.51,2119.02 7674.48,2125 7724.84,2125 7748.86,2149.02 7748.86,2438.39 7723.52,2463.73 7723.52,2622.39 7765.19,2664.06 7765.19,3145.04 v1(7795.19,3175.04) ; v1@7785.69,3175.04 cw(c7762.76,3175.04) 7778.97,3158.82 cw(c7795.19,3142.61) v1@7795.19,3165.54 ; v1@7789.69,3175.04 cw(c7776.41,3175.04) 7785.8,3165.65 cw(c7795.19,3156.26) v1@7795.19,3169.54
  MidLayer2 w4: v1(7795.19,3175.04) v1(7954.86,3175.04) ; v1@7799.08,3171.15 cw(c7808.47,3161.76) 7808.47,3175.04 cw(c7808.47,3188.32) v1@7799.08,3178.93 ; v1@7801.91,3168.32 cw(c7818.13,3152.11) 7818.13,3175.04 cw(c7818.13,3197.98) v1@7801.91,3181.76 ; v1@7948.14,3168.32 ccw(c7931.92,3152.11) 7931.92,3175.04 ccw(c7931.92,3197.98) v1@7948.14,3181.76 ; v1@7950.97,3171.15 ccw(c7941.58,3161.76) 7941.58,3175.04 ccw(c7941.58,3188.32) v1@7950.97,3178.93
HOST_SRAM.NBHE: U30.C7 U47.40 | length 2490.5
  Top Layer w4: v1(7961.19,3241.71) 7971.52,3241.71 7973.51,3239.72 ; v1@7965.08,3245.6 ccw(c7979.26,3259.78) U47.40@7979.26,3239.72 ; v1@7967.91,3234.99 cw(c7979.34,3223.56) U47.40@7979.34,3239.72 ; v1@7967.91,3248.43 ccw(c7988.91,3269.43) U47.40@7988.91,3239.72 ; U47.40@7979.79,3235.96 ccw(c7973.51,3232.6) 7973.51,3239.72 ; U47.40@7979.79,3243.49 cw(c7973.51,3246.85) 7973.51,3239.72 ; U47.40@8004.41,3239.72 7973.51,3239.72
  Top Layer w8: U30.C7@7305.28,2002.8 v2(7324.96,2022.48) ; U30.C7@7305.28,2008.64 ccw(c7305.28,2022.74) 7315.25,2012.77 ccw(c7325.22,2002.8) U30.C7@7311.12,2002.8 ; v2@7315.96,2022.48 cw(c7294.23,2022.48) 7309.6,2007.12 cw(c7324.96,1991.75) v2@7324.96,2013.48
  MidLayer1 w4: v2(7324.96,2022.48) 7344.52,2042.04 7344.52,2108.71 7356.86,2121.04 7443.19,2121.04 7463.86,2141.71 7463.86,2300.04 7472.19,2308.37 7491.44,2308.37 7512.62,2287.19 7528.04,2287.19 7556.86,2258.37 7556.86,2138.73 7565.19,2130.39 ; v2@7324.96,2029.48 ccw(c7324.96,2046.38) 7336.91,2034.43 ccw(c7348.86,2022.48) v2@7331.96,2022.48 ; v2@7324.96,2033.48 ccw(c7324.96,2060.04) 7343.74,2041.26 ccw(c7362.51,2022.48) v2@7335.96,2022.48 ; v1@7558.75,2115.69 ccw(c7545.19,2130.39) 7565.19,2130.39 ; v1@7561.46,2112.75 ccw(c7553.61,2121.26) 7565.19,2121.26 ccw(c7576.77,2121.26) v1@7568.92,2112.75 ; v1(7565.19,2108.71) 7565.19,2130.39 ; v1@7571.63,2115.69 cw(c7585.19,2130.39) 7565.19,2130.39
  MidLayer2 w4: v1(7565.19,2108.71) 7589.86,2133.37 7745,2133.37 7745,2133.71 7756.86,2145.56 7756.86,2447.06 7806.86,2497.06 7806.86,2900.04 7981.86,3075.04 7981.86,3221.04 v1(7961.19,3241.71) ; v1@7565.19,2114.21 ccw(c7565.19,2127.49) 7574.58,2118.1 ccw(c7583.97,2108.71) v1@7570.69,2108.71 ; v1@7565.19,2118.21 ccw(c7565.19,2141.14) 7581.41,2124.93 ccw(c7597.63,2108.71) v1@7574.69,2108.71 ; v1@7961.19,3232.21 cw(c7961.19,3209.27) 7977.41,3225.49 cw(c7993.63,3241.71) v1@7970.69,3241.71 ; v1@7961.19,3236.21 cw(c7961.19,3222.93) 7970.58,3232.32 cw(c7979.97,3241.71) v1@7966.69,3241.71
HOST_SRAM.NBLE: U30.A4 U47.39 | length 1919.4
  Top Layer w4: v1@7866.81,2420.43 ccw(c7850.59,2436.64) 7873.52,2436.64 ccw(c7896.46,2436.64) v1@7880.24,2420.43 ; v1@7869.64,2417.6 ccw(c7860.25,2426.99) 7873.52,2426.99 ccw(c7886.8,2426.99) v1@7877.41,2417.6 ; v1(7873.52,2413.71) 7873.52,2474.04 7891.52,2492.04 7891.52,2575 7881.86,2584.67 7881.86,3198.23 7891.86,3208.23 U47.39@8004.41,3208.23 ; U47.39@7981.19,3202.57 ccw(c7967.54,3188.91) 7967.54,3208.23 ccw(c7967.54,3227.54) U47.39@7981.19,3213.88
  Top Layer w8: U30.A4@7384.02,2120.91 v2(7403.7,2140.59) ; U30.A4@7384.02,2126.75 ccw(c7384.02,2140.85) 7393.99,2130.88 ccw(c7403.96,2120.91) U30.A4@7389.86,2120.91 ; v2@7394.7,2140.59 cw(c7372.97,2140.59) 7388.34,2125.23 cw(c7403.7,2109.86) v2@7403.7,2131.59
  Bottom Layer w4: v2(7403.7,2140.59) 7415.19,2140.59 7416.31,2141.71 7736.86,2141.71 7748.52,2153.37 7748.52,2353.52 7808.71,2413.71 v1(7873.52,2413.71) ; v2@7408.65,2135.64 cw(c7423.3,2120.99) 7423.3,2141.71 ; v2@7408.65,2145.54 ccw(c7417.9,2154.79) 7417.9,2141.71 ; v2@7411.48,2132.81 cw(c7432.95,2111.34) 7432.95,2141.71 ; v2@7411.48,2148.37 ccw(c7427.56,2164.45) 7427.56,2141.71 ; v1@7866.81,2406.99 ccw(c7850.59,2390.77) 7850.59,2413.71 ccw(c7850.59,2436.64) v1@7866.81,2420.43 ; v1@7869.64,2409.82 ccw(c7860.25,2400.43) 7860.25,2413.71 ccw(c7860.25,2426.99) v1@7869.64,2417.6
HOST_SRAM.NCS: U30.F9 U47.6 | length 2495.5
  Top Layer w4: U47.6@7555.59,3208.23 7585.67,3208.23 ; U47.6@7580.41,3204.87 cw(c7585.67,3202.43) 7585.67,3208.23 ; U47.6@7580.41,3211.59 ccw(c7585.67,3214.03) 7585.67,3208.23 ; v1(7599.19,3194.71) 7585.67,3208.23
  Top Layer w8: U30.F9@7187.17,1924.06 v2(7206.85,1943.74) ; U30.F9@7187.17,1929.9 ccw(c7187.17,1944) 7197.14,1934.03 ccw(c7207.11,1924.06) U30.F9@7193.01,1924.06 ; v2@7197.85,1943.74 cw(c7176.12,1943.74) 7191.49,1928.38 cw(c7206.85,1913.01) v2@7206.85,1934.74
  MidLayer1 w4: v2(7206.85,1943.74) 7227.15,1964.04 7256.86,1964.04 7266.52,1973.71 7266.52,1991.71 7277.19,2002.37 7423.52,2002.37 7497.81,2076.66 7497.81,2117.38 7481.86,2133.33 v1(7481.86,2283.37) ; v2@7206.85,1950.74 ccw(c7206.85,1967.64) 7218.8,1955.69 ccw(c7230.75,1943.74) v2@7213.85,1943.74 ; v2@7206.85,1954.74 ccw(c7206.85,1981.3) 7225.63,1962.52 ccw(c7244.41,1943.74) v2@7217.85,1943.74 ; v1@7475.14,2276.66 cw(c7458.92,2260.44) 7481.86,2260.44 cw(c7504.79,2260.44) v1@7488.57,2276.66 ; v1@7477.97,2279.49 cw(c7468.58,2270.1) 7481.86,2270.1 cw(c7495.14,2270.1) v1@7485.75,2279.49
  MidLayer2 w4: v1@7475.14,2290.09 ccw(c7458.92,2306.31) 7481.86,2306.31 ccw(c7504.79,2306.31) v1@7488.57,2290.09 ; v1@7477.97,2287.26 ccw(c7468.58,2296.65) 7481.86,2296.65 ccw(c7495.14,2296.65) v1@7485.75,2287.26 ; v1(7481.86,2283.37) 7481.86,2322.06 7515.19,2355.39 7515.19,2423.37 7581.86,2490.04 7581.86,2708.37 7606.86,2733.37 7623.52,2733.37 7656.86,2700.04 7680.23,2700.04 7690,2709.81 7690,2741.71 7668.97,2762.74 7668.97,2818.78 7715.19,2865 7715.19,3300.04 7656.86,3358.37 7597.19,3358.37 7581.86,3343.04 7581.86,3212.04 v1(7599.19,3194.71) ; v1@7589.69,3194.71 ccw(c7566.76,3194.71) 7582.97,3210.93 ccw(c7599.19,3227.14) v1@7599.19,3204.21 ; v1@7593.69,3194.71 ccw(c7580.41,3194.71) 7589.8,3204.1 ccw(c7599.19,3213.49) v1@7599.19,3200.21
HOST_SRAM.NOE: U30.B5 U47.41 | length 2271.1
  Top Layer w4: v1(7810.52,2327.37) 7798.19,2339.71 7798.19,2463.19 7814.86,2479.86 7814.86,2558.04 7823.52,2566.71 7865.19,2608.37 7865.19,3366.37 7886.19,3387.37 8029.53,3387.37 8038.53,3378.37 8038.53,3272.89 8036.86,3271.22 ; U47.41@8004.41,3271.22 8036.86,3271.22 ; U47.41@8028.64,3266.8 cw(c8036.86,3261.36) 8036.86,3271.22 ; U47.41@8028.64,3275.64 ccw(c8036.86,3281.08) 8036.86,3271.22
  Top Layer w8: U30.B5@7344.65,2081.54 v2(7364.33,2101.22) ; U30.B5@7344.65,2087.38 ccw(c7344.65,2101.48) 7354.62,2091.51 ccw(c7364.59,2081.54) U30.B5@7350.49,2081.54 ; v2@7355.33,2101.22 cw(c7333.6,2101.22) 7348.97,2085.86 cw(c7364.33,2070.49) v2@7364.33,2092.22
  Bottom Layer w4: v2@7364.12,2100.24 ccw(c7367.94,2117.95) 7380.75,2105.14 ; v2(7364.33,2101.22) 7376.83,2101.22 7396.32,2120.71 ; v2@7364.96,2104.15 ccw(c7369.79,2126.48) 7385.94,2110.33 ; v2@7365.81,2108.06 ccw(c7371.63,2135.02) 7391.13,2115.52 ; v2@7366.65,2111.97 ccw(c7373.47,2143.55) 7396.32,2120.71 ; v1@7801.02,2327.37 cw(c7778.09,2327.37) 7794.31,2311.16 cw(c7810.52,2294.94) v1@7810.52,2317.87 ; v1@7805.02,2327.37 cw(c7791.75,2327.37) 7801.14,2317.99 cw(c7810.52,2308.6) v1@7810.52,2321.87 ; v1(7810.52,2327.37) 7775,2291.85 7775,2168.54 7739.84,2133.37 7478.19,2133.37 7465.52,2120.71 7396.32,2120.71
HOST_SRAM.NWE: U30.D6 U47.17 | length 1627.4
  Top Layer w4: U47.17@7555.59,2861.77 7591.15,2861.77 ; U47.17@7579.09,2856.41 cw(c7591.15,2845.52) 7591.15,2861.77 ; U47.17@7579.09,2867.13 ccw(c7591.15,2878.02) 7591.15,2861.77 ; v1(7728.52,2081.37) 7748.52,2101.37 7748.52,2505.39 7730.54,2523.38 7730.54,2722.39 7591.15,2861.77 ; v1@7728.52,2086.87 ccw(c7728.52,2100.15) 7737.91,2090.76 ccw(c7747.3,2081.37) v1@7734.02,2081.37 ; v1@7728.52,2090.87 ccw(c7728.52,2113.81) 7744.74,2097.59 ccw(c7760.96,2081.37) v1@7738.02,2081.37
  Top Layer w8: U30.D6@7265.91,2042.17 v2(7285.59,2061.85) ; U30.D6@7265.91,2048.01 ccw(c7265.91,2062.11) 7275.88,2052.14 ccw(c7285.85,2042.17) U30.D6@7271.75,2042.17 ; v2@7276.59,2061.85 cw(c7254.86,2061.85) 7270.23,2046.49 cw(c7285.59,2031.12) v2@7285.59,2052.85
  Bottom Layer w4: v2(7285.59,2061.85) 7305.12,2081.37 7543.8,2081.37 7544.96,2082.54 7727.36,2082.54 v1(7728.52,2081.37) ; v2@7285.59,2068.85 ccw(c7285.59,2085.75) 7297.54,2073.8 ; v2@7285.59,2072.85 ccw(c7285.59,2099.41) 7304.37,2080.63 ccw(c7323.14,2061.85) v2@7296.59,2061.85 ; v2@7292.59,2061.85 cw(c7309.49,2061.85) 7297.54,2073.8 ; 7702.77,2082.54 cw(c7702.77,2055.62) v1@7721.81,2074.66 ; 7708.4,2082.54 ccw(c7708.4,2101.49) v1@7721.81,2088.09 ; 7712.43,2082.54 cw(c7712.43,2065.28) v1@7724.64,2077.49
HOST_USB.D0: U30.H4 U56.18 | length 6682
  Top Layer w8: U30.H4@7108.43,2120.91 v2(7128.11,2140.59) ; U30.H4@7108.43,2126.75 ccw(c7108.43,2140.85) 7118.4,2130.88 ccw(c7128.37,2120.91) U30.H4@7114.27,2120.91 ; v2@7119.11,2140.59 cw(c7097.38,2140.59) 7112.75,2125.23 cw(c7128.11,2109.86) v2@7128.11,2131.59
  MidLayer2 w4: v5(6733,6203.9) 7544.67,6203.9 v1(7665.19,6083.37) ; v5@6738.66,6198.24 cw(c6752.31,6184.58) 6752.31,6203.9 cw(c6752.31,6223.21) v5@6738.66,6209.55 ; v2@7117.11,2140.59 ccw(c7090.55,2140.59) 7109.33,2159.37 ccw(c7128.11,2178.15) v2@7128.11,2151.59 ; v2@7121.11,2140.59 ccw(c7104.21,2140.59) 7116.16,2152.54 ccw(c7128.11,2164.49) v2@7128.11,2147.59 ; v2(7128.11,2140.59) 7107.99,2160.71 7080.86,2160.71 7069.52,2172.04 7069.52,2379.37 7256.86,2566.71 7256.86,2681.69 7573.52,2998.36 7573.52,3359.37 7680.86,3466.71 8231.86,3466.71 v1(8373.52,3608.37) ; v1@7655.69,6083.37 ccw(c7632.76,6083.37) 7648.97,6099.59 ccw(c7665.19,6115.81) v1@7665.19,6092.87 ; v1@7659.69,6083.37 ccw(c7646.41,6083.37) 7655.8,6092.76 ccw(c7665.19,6102.15) v1@7665.19,6088.87 ; v1@8364.02,3608.37 cw(c8341.09,3608.37) 8357.31,3592.16 cw(c8373.52,3575.94) v1@8373.52,3598.87 ; v1@8368.02,3608.37 cw(c8354.75,3608.37) 8364.14,3598.99 cw(c8373.52,3589.6) v1@8373.52,3602.87
  Bottom Layer w4: v1(7665.19,6083.37) 7867.59,6083.37 7990.81,5960.15 7990.81,5869.19 7990.81,5224.42 8024.41,5190.82 8265.19,4950.04 8265.19,4443.88 8237,4415.69 8237,4136.69 8223.36,4123.05 8223.36,3770.32 8357.84,3635.85 8357.84,3624.06 v1(8373.52,3608.37) ; v1@7669.08,6079.49 cw(c7678.47,6070.1) 7678.47,6083.37 cw(c7678.47,6096.65) v1@7669.08,6087.26 ; v1@7671.91,6076.66 cw(c7688.13,6060.44) 7688.13,6083.37 cw(c7688.13,6106.31) v1@7671.91,6090.09
  Bottom Layer w8: v5(6733,6203.9) U56.18@6764.33,6203.9 ; v5@6737.24,6199.65 cw(c6747.48,6189.41) 6747.48,6203.9 cw(c6747.49,6218.38) v5@6737.24,6208.14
